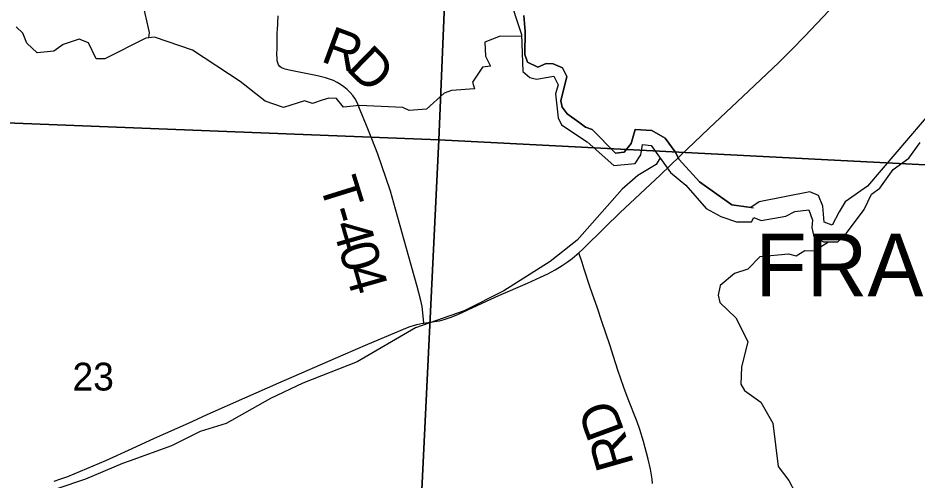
# Model space of a CAD drawing. Extents: x 0 to 34, y 0 to 22.
# Drawn here: x 3.441 to 4.796, y 16.998 to 17.694 of the extents above; entities that cross this region are included whole.
import ezdxf

# ---------------------------------------------------------------- set-up
doc = ezdxf.new("R2010")
doc.units = 0
for name, color, linetype in [('GM_X_Corporation_Text', 7, 'Continuous'), ('GM_X_County_Road', 7, 'Continuous'), ('GM_X_County_Road_Text', 7, 'Continuous'), ('GM_X_Minor_River', 7, 'Continuous'), ('GM_X_Section', 7, 'Continuous'), ('GM_X_Section_Text', 7, 'Continuous'), ('GM_X_Township_Road', 7, 'Continuous'), ('GM_X_Township_Road_Text', 7, 'Continuous')]:
    doc.layers.add(name, color=color, linetype=linetype)

msp = doc.modelspace()

# ---------------------------------------------------------------- linework, layer by layer
at = {"layer": 'GM_X_County_Road'}
for points in [[(4.2855, 17.341), (4.2918, 17.3468), (4.325, 17.3794), (4.3475, 17.4009), (4.4085, 17.4585), (4.4377, 17.4863), (4.4812, 17.528), (4.5413, 17.5847), (4.5865, 17.6273), (4.6065, 17.6468), (4.626, 17.6668), (4.6622, 17.7052), (4.6715, 17.7152)], [(4.0522, 17.2353), (4.068, 17.2375), (4.0755, 17.2385), (4.0829, 17.2406), (4.0917, 17.2435), (4.1031, 17.2482), (4.1398, 17.2651), (4.1653, 17.2766), (4.208, 17.2952), (4.2278, 17.3041), (4.239, 17.3095), (4.2499, 17.3154), (4.2604, 17.3218), (4.2681, 17.327), (4.2756, 17.3325), (4.2827, 17.3384), (4.2855, 17.341)], [(4.3964, 16.994), (4.396, 17.0002), (4.3951, 17.0063), (4.3934, 17.0154), (4.3898, 17.0304), (4.3827, 17.0573), (4.3774, 17.075), (4.3734, 17.0866), (4.3599, 17.121), (4.3535, 17.1383), (4.3443, 17.1645), (4.3377, 17.185), (4.332, 17.2025), (4.326, 17.2199), (4.3202, 17.2374), (4.3129, 17.259), (4.3059, 17.2786), (4.3019, 17.2903), (4.2935, 17.3166), (4.2905, 17.3266), (4.2855, 17.341)], [(3.4954, 16.9974), (3.5042, 17.0002), (3.5158, 17.0045), (3.5445, 17.0163), (3.5731, 17.0285), (3.6127, 17.0464), (3.6466, 17.0619), (3.6975, 17.0849), (3.7258, 17.0977), (3.7826, 17.1229), (3.8338, 17.1455), (3.9307, 17.1873), (3.9677, 17.2035), (4.0084, 17.2206), (4.0179, 17.2248), (4.025, 17.2275), (4.0316, 17.2299), (4.0418, 17.233), (4.0508, 17.2351), (4.0522, 17.2353)]]:
    msp.add_lwpolyline(points, dxfattribs=at)
at = {"layer": 'GM_X_Minor_River'}
for points in [[(3.6381, 17.6644), (3.6391, 17.6722), (3.6284, 17.7184), (3.5968, 17.7532), (3.593, 17.7631), (3.5602, 17.8078), (3.5553, 17.8199), (3.5328, 17.8672), (3.5202, 17.8816), (3.5077, 17.8869), (3.4753, 17.9277), (3.4526, 17.9447), (3.3812, 17.9695)], [(4.1793, 17.7304), (4.1992, 17.6694), (4.2013, 17.6136), (4.2115, 17.6049), (4.2218, 17.6023), (4.2479, 17.6066), (4.2544, 17.5937), (4.2503, 17.58), (4.2542, 17.544), (4.2595, 17.5334), (4.2983, 17.5077), (4.3382, 17.4722), (4.3704, 17.4753), (4.3787, 17.4886), (4.3813, 17.5038), (4.3945, 17.5023), (4.4238, 17.4618), (4.4466, 17.4429), (4.4774, 17.4078), (4.4991, 17.3957), (4.523, 17.3874), (4.5457, 17.3875)], [(4.5443, 17.409), (4.5157, 17.4132), (4.4671, 17.4479), (4.4367, 17.4812), (4.4306, 17.493), (4.4157, 17.5134), (4.3952, 17.5251), (4.3702, 17.5265), (4.3642, 17.5053), (4.354, 17.4923), (4.3408, 17.4908), (4.3054, 17.5267), (4.2955, 17.5301), (4.2857, 17.5376), (4.2678, 17.5501), (4.2602, 17.5603), (4.2583, 17.5698), (4.2676, 17.6062), (4.2608, 17.6191), (4.2471, 17.6251), (4.2365, 17.6259), (4.2236, 17.6201), (4.2081, 17.6277), (4.2042, 17.6394), (4.2049, 17.6739), (4.2025, 17.6978)], [(4.2025, 17.6978), (4.2049, 17.6739), (4.2042, 17.6394), (4.2081, 17.6277), (4.2236, 17.6201), (4.2365, 17.6259), (4.2471, 17.6251), (4.2608, 17.6191), (4.2676, 17.6062), (4.2583, 17.5698), (4.2602, 17.5603), (4.2678, 17.5501), (4.2857, 17.5376), (4.2955, 17.5301), (4.3054, 17.5267), (4.3408, 17.4908), (4.354, 17.4923), (4.3642, 17.5053), (4.3702, 17.5265), (4.3952, 17.5251), (4.4157, 17.5134), (4.4306, 17.493), (4.4367, 17.4812), (4.4671, 17.4479), (4.5157, 17.4132), (4.5483, 17.4084)], [(4.1993, 17.6662), (4.167, 17.667), (4.1439, 17.6578), (4.1451, 17.6366), (4.1524, 17.6218), (4.1403, 17.6203), (4.1252, 17.5975), (4.1282, 17.5876), (4.0938, 17.5852), (4.0828, 17.581), (4.0563, 17.557), (4.0302, 17.5551), (4.0207, 17.5596), (3.9551, 17.5628), (3.9313, 17.5601), (3.9206, 17.5729), (3.9093, 17.5737), (3.899, 17.5706), (3.8843, 17.5656), (3.8725, 17.5694), (3.8407, 17.5598), (3.813, 17.5692), (3.7754, 17.5987), (3.7036, 17.6458), (3.6467, 17.6654), (3.6335, 17.6638), (3.5718, 17.6329), (3.5585, 17.6329), (3.5471, 17.6571), (3.5331, 17.6624), (3.5088, 17.6544), (3.4952, 17.6444), (3.4698, 17.6417), (3.4543, 17.6565), (3.4481, 17.6712), (3.4383, 17.6811)], [(4.8229, 17.5616), (4.72, 17.4413), (4.6864, 17.4177), (4.6777, 17.4028), (4.6672, 17.3827), (4.6547, 17.3872), (4.6531, 17.4111), (4.6462, 17.427), (4.6333, 17.4326), (4.5571, 17.4179), (4.5443, 17.409)], [(4.5457, 17.3875), (4.5489, 17.3943), (4.5603, 17.3894), (4.5974, 17.396), (4.6106, 17.4029), (4.6319, 17.4057), (4.6372, 17.3901), (4.6362, 17.3791), (4.6392, 17.3651), (4.6541, 17.3576), (4.6757, 17.3573), (4.6885, 17.3706), (4.7152, 17.406), (4.7261, 17.4292), (4.7386, 17.438), (4.7589, 17.4662), (4.7824, 17.4833), (4.7997, 17.5069)], [(4.4079, 17.4838), (4.4018, 17.4739), (4.3746, 17.4575), (4.3508, 17.4366), (4.2828, 17.3601), (4.2424, 17.3278), (4.1728, 17.2839), (4.1126, 17.2538), (4.0396, 17.2281), (3.9518, 17.177), (3.8701, 17.1449), (3.8213, 17.1216), (3.7547, 17.0842), (3.7154, 17.072), (3.6722, 17.0506), (3.6086, 17.0273), (3.5984, 17.0238), (3.5424, 17.0005), (3.455, 16.971)], [(4.5399, 17.3162), (4.5587, 17.3355), (4.6011, 17.3395), (4.6128, 17.3362), (4.6257, 17.3446), (4.6401, 17.3439), (4.6616, 17.3575)], [(4.5399, 17.3162), (4.5198, 17.31), (4.4983, 17.2917), (4.4953, 17.2773), (4.4976, 17.2663), (4.5219, 17.2433), (4.5399, 17.2073), (4.5305, 17.169), (4.5295, 17.1435), (4.5352, 17.1337), (4.5595, 17.1163)], [(4.5595, 17.1163), (4.5776, 17.0849), (4.5859, 17.0193), (4.6019, 16.9985), (4.621, 16.9625), (4.631, 16.9386), (4.6318, 16.9288), (4.6142, 16.8802), (4.6098, 16.8376), (4.6191, 16.8092), (4.6271, 16.7945), (4.6356, 16.7569)]]:
    msp.add_lwpolyline(points, dxfattribs=at)
at = {"layer": 'GM_X_Section'}
for points in [[(4.1166, 18.5074), (4.0746, 17.5111), (3.0654, 17.5504), (3.0927, 18.5447)], [(4.1166, 18.5074), (5.1195, 18.4619), (5.0805, 17.4591), (4.0746, 17.5111)], [(3.0654, 17.5504), (4.0746, 17.5111), (4.0244, 16.4784), (4.0204, 16.4785), (3.5484, 16.5002), (3.0372, 16.514)], [(4.0746, 17.5111), (5.0805, 17.4591), (5.0528, 16.4469), (4.8222, 16.4519), (4.5034, 16.4581), (4.0244, 16.4784)]]:
    msp.add_lwpolyline(points, close=True, dxfattribs=at)
at = {"layer": 'GM_X_Township_Road'}
msp.add_lwpolyline([(4.0522, 17.2353), (4.0508, 17.2508), (4.0494, 17.26), (4.0474, 17.2691), (4.042, 17.2901), (4.0294, 17.3349), (4.0096, 17.4067), (4.0017, 17.4335), (3.995, 17.4542), (3.9827, 17.4893), (3.974, 17.5125), (3.9659, 17.5327), (3.9563, 17.5555), (3.9515, 17.567), (3.9485, 17.5724), (3.945, 17.5775), (3.941, 17.5822), (3.9366, 17.5866), (3.9318, 17.5906), (3.9268, 17.5942), (3.9214, 17.5974), (3.9159, 17.6001), (3.9101, 17.6024), (3.9042, 17.6042), (3.8921, 17.607), (3.8495, 17.6156), (3.8435, 17.6171), (3.8406, 17.6181), (3.8378, 17.6195), (3.8354, 17.6214), (3.8335, 17.6239), (3.8322, 17.6267), (3.8314, 17.6297), (3.8311, 17.6328), (3.8309, 17.6404), (3.8311, 17.6482), (3.8314, 17.665), (3.8314, 17.6729), (3.8316, 17.676), (3.8326, 17.6977)], dxfattribs=at)

# ---------------------------------------------------------------- texts
at = {"layer": 'GM_X_Corporation_Text'}
msp.add_text('FRAZEYSBURG', height=0.094697, rotation=0, dxfattribs=at).set_placement((4.5512, 17.2753))
at = {"layer": 'GM_X_County_Road_Text'}
for s, rotation, p in [('D', 110.1814, (4.3546, 17.0724)), ('R', 105.8719, (4.3688, 17.0231))]:
    msp.add_text(s, height=0.0568, rotation=rotation, dxfattribs=at).set_placement(p)
at = {"layer": 'GM_X_Section_Text'}
msp.add_text('23', height=0.04186, rotation=0, dxfattribs=at).set_placement((3.5231, 17.1338))
at = {"layer": 'GM_X_Township_Road_Text'}
for s, rotation, p in [('R', 339.6998, (3.8952, 17.6296)), ('D', 315.7006, (3.9337, 17.6167)), ('T', 287.2518, (3.8945, 17.4451)), ('-', 286.3732, (3.9071, 17.4047)), ('4', 286.1205, (3.9136, 17.3824)), ('0', 285.9526, (3.9233, 17.3488)), ('4', 285.9097, (3.933, 17.3152))]:
    msp.add_text(s, height=0.0568, rotation=rotation, dxfattribs=at).set_placement(p)

doc.saveas('drawing.dxf')
